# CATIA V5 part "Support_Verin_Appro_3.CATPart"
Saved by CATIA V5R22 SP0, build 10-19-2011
Part number: Support_Verin_Flacon_AV
Bounding box of the stored display mesh (mm): x -18.5 to 18.5, y -24 to 0, z -20 to 18.5
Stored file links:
  C:\Users\La forge\Desktop\CAO_PER_pick&place_2023A\Sous_Ensemble_Flacon\Verin\Support_Verin_Appro_3.CATPart
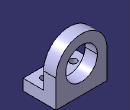
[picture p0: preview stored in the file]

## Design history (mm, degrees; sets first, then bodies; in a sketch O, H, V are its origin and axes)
Body1 (main body)
  Sketch1 on zx-plane, origin (0, 0, 0), H (-1, 0, 0), V (0, 0, 1)
    circle A1 centre (0, 0) radius 11.5
    arc A2 centre (0, 0) radius 18.5 from (18.5, 0) to (-18.5, 0) ccw
    line L1 (18.5, -20) -> (-18.5, -20)
    line L2 (-18.5, -20) -> (-18.5, 0)
    line L3 (18.5, 0) -> (18.5, -20)
    radius A1 = 11.5
    distance A2 A1 = 7
    length L2 = 20
    distance L1 H = 20
    horizontal: L1 H
    vertical: L2 V, L3 V
    tangency: L3 A2
  Pad1: profile Sketch1, direction (0, -1, 0), length 9
  Sketch2 on end face of Pad1, origin (0, -9, 0), H (1, 0, 0), V (0, 0, 1)
    point P1 (18.5, -20)
    line L1 (18.5, -20) -> (-18.5, -20)
    line L2 (-18.5, -20) -> (-18.5, -12)
    line L3 (-18.5, -12) -> (18.5, -12)
    line L4 (18.5, -12) -> (18.5, -20)
    point P2 (-18.5, -20)
    reference projected point E1 (18.5, -20) from vertex [face of Pad1 from Sketch1.L1 | end face of Pad1 | face of Pad1 from Sketch1.L2]
    reference projected point E2 (-18.5, -20) from vertex [face of Pad1 from Sketch1.L3 | end face of Pad1 | face of Pad1 from Sketch1.L1]
    distance L3 H = 12
    horizontal: L1 H, L3 H
    vertical: L2 V, L4 V
    coincidence: P1 E1, E2 P2
  Pad2: profile Sketch2, direction (0, -1, 0), length 15
  Sketch3 on face of Pad2 from Sketch2.L3, origin (5.7564, -18.4322, -12), H (1, 0, 0), V (0, 1, 0)
    point P1 (4.7436, 1.9322)
    reference projected line E1 (12.7436, -5.5678) -> (-24.2564, -5.5678) from edge [face of Pad2 from Sketch2.L3 | end face of Pad2]
    reference projected line E2 (-24.2564, 9.4322) -> (12.7436, 9.4322) from edge [end face of Pad1 | face of Pad1 from Sketch1.A2]
    reference projected line E3 (12.7436, 9.4322) -> (12.7436, -5.5678) from edge [face of Pad2 from Sketch2.L3 | face of Pad2]
    distance P1 E3 = 8
    equidistance: E1 E2 P1
  Hole1: placed by Sketch3, at (10.5, -16.5, -12) direction (0, 0, -1), diameter 5, through (limit type 6)
  Mirror1: of Hole1, about yz-plane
